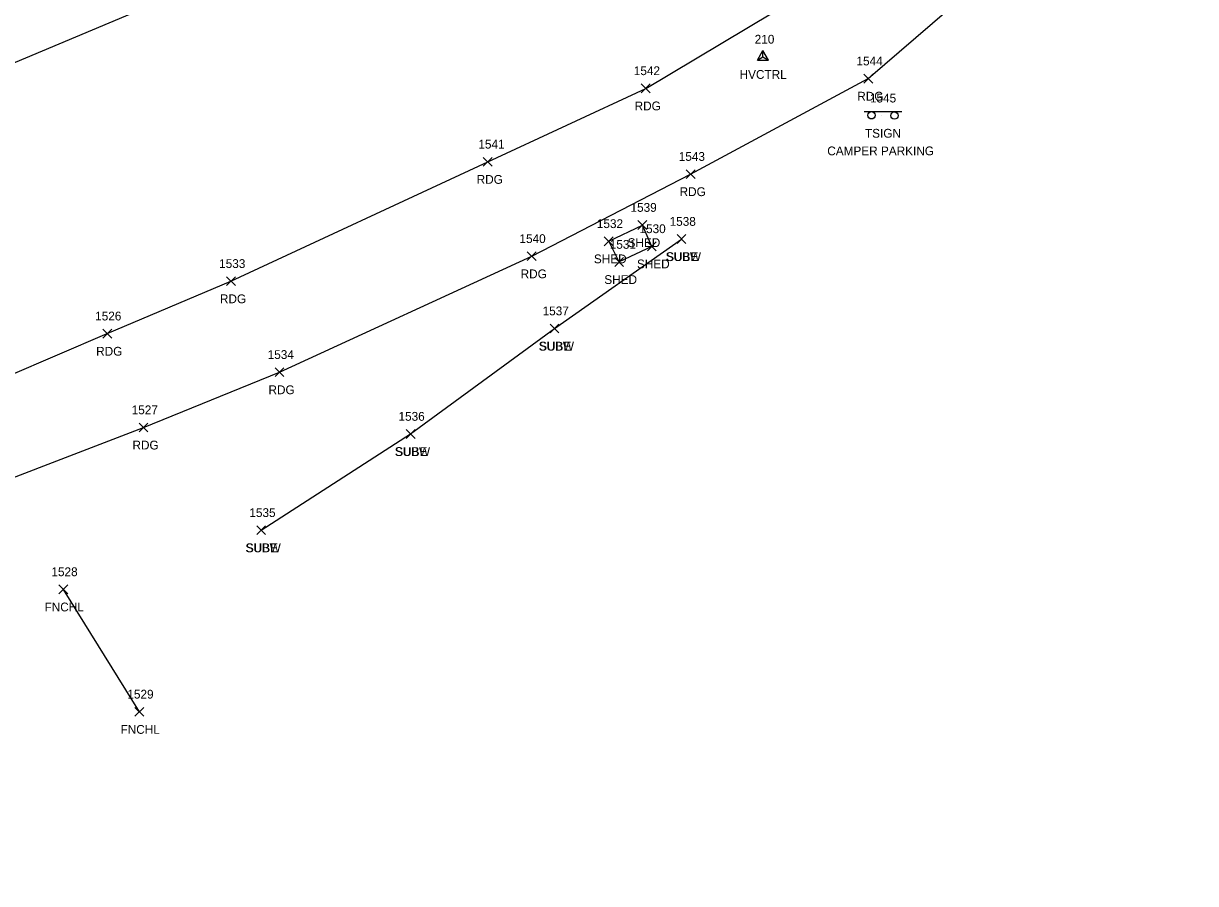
# Model space of a CAD drawing. Extents: x 1481523 to 1489083, y 884156 to 893756.
# Drawn here: x 1486886.1 to 1487152.1, y 887971.3 to 888166.7 of the extents above; entities that cross this region are included whole.
import ezdxf

# ---------------------------------------------------------------- set-up
doc = ezdxf.new("R2010")
doc.units = 0
for name, color, linetype in [('C_A', 7, 'Continuous'), ('C_I', 7, 'Continuous'), ('CPSM', 7, 'Continuous'), ('L_A', 7, 'Continuous'), ('L_I', 7, 'Continuous'), ('L_TIC', 7, 'Continuous'), ('LBC', 7, 'Continuous'), ('LFNC', 7, 'Continuous'), ('P_A', 7, 'Continuous'), ('P_I', 7, 'Continuous'), ('P_TIC', 7, 'Continuous'), ('PEU', 7, 'Continuous'), ('S_A', 7, 'Continuous'), ('S_C', 7, 'Continuous'), ('S_I', 7, 'Continuous'), ('SSGN', 7, 'Continuous'), ('U_A', 7, 'Continuous'), ('U_I', 7, 'Continuous'), ('U_TIC', 7, 'Continuous'), ('UE', 7, 'Continuous'), ('UW', 7, 'Continuous')]:
    doc.layers.add(name, color=color, linetype=linetype)

msp = doc.modelspace()

# ---------------------------------------------------------------- linework, layer by layer
at = {"layer": 'CPSM'}
for p, q in [((1487052.67, 888158.34), (1487053.92, 888160.5)), ((1487052.67, 888158.34), (1487053.92, 888159.06)), ((1487052.67, 888158.34), (1487055.17, 888158.34)), ((1487055.17, 888158.34), (1487053.92, 888160.5)), ((1487053.92, 888159.06), (1487053.92, 888160.5)), ((1487053.92, 888159.06), (1487053.92, 888159.06)), ((1487053.92, 888159.06), (1487055.17, 888158.34))]:
    msp.add_line(p, q, dxfattribs=at)
at = {"layer": 'L_TIC'}
for points in [[(1487025.55, 888119.87), (1487027.55, 888121.87)], [(1487027.55, 888119.87), (1487025.55, 888121.87)], [(1487025.55, 888119.87), (1487027.55, 888121.87)], [(1487027.55, 888119.87), (1487025.55, 888121.87)], [(1487017.9, 888116.18), (1487019.9, 888118.18)], [(1487019.9, 888116.18), (1487017.9, 888118.18)], [(1487027.67, 888115.03), (1487029.67, 888117.03)], [(1487029.67, 888115.03), (1487027.67, 888117.03)], [(1487027.67, 888115.03), (1487029.67, 888117.03)], [(1487029.67, 888115.03), (1487027.67, 888117.03)], [(1487020.27, 888111.48), (1487022.27, 888113.48)], [(1487022.27, 888111.48), (1487020.27, 888113.48)], [(1486894.1, 888037.13), (1486896.1, 888039.13)], [(1486896.1, 888037.13), (1486894.1, 888039.13)], [(1486911.35, 888009.33), (1486913.35, 888011.33)], [(1486913.35, 888009.33), (1486911.35, 888011.33)]]:
    msp.add_lwpolyline(points, dxfattribs=at)
at = {"layer": 'LBC'}
for points in [[(1487028.67, 888116.03), (1487021.27, 888112.48), (1487018.9, 888117.18), (1487026.55, 888120.87)], [(1487028.67, 888116.03), (1487026.55, 888120.87)]]:
    msp.add_lwpolyline(points, dxfattribs=at)
at = {"layer": 'LFNC'}
for points in [[(1487123.63, 888696.4), (1487124.91, 888638.27), (1487126.15, 888568.63), (1487127.36, 888492.8), (1487107.41, 888449.36), (1487090.77, 888413.6), (1487074.34, 888378.07), (1487054.02, 888334.46), (1487033.84, 888290.91), (1487013.45, 888247.02), (1487001.64, 888221.58), (1486993.21, 888204.38), (1486939.48, 888181.13), (1486867.52, 888150.81), (1486821.88, 888131.48), (1486777.19, 888112.51), (1486741.33, 888097.33), (1486705.19, 888082.4), (1486701.15, 888103.56), (1486696.51, 888133.19), (1486722.31, 888152.64)], [(1486895.1, 888038.13), (1486912.35, 888010.33)]]:
    msp.add_lwpolyline(points, dxfattribs=at)
at = {"layer": 'P_TIC'}
for points in [[(1487076.83, 888153.12), (1487078.83, 888155.12)], [(1487078.83, 888153.12), (1487076.83, 888155.12)], [(1487026.3, 888150.91), (1487028.3, 888152.91)], [(1487028.3, 888150.91), (1487026.3, 888152.91)], [(1486990.44, 888134.23), (1486992.44, 888136.23)], [(1486992.44, 888134.23), (1486990.44, 888136.23)], [(1487036.5, 888131.44), (1487038.5, 888133.44)], [(1487038.5, 888131.44), (1487036.5, 888133.44)], [(1487000.42, 888112.78), (1487002.42, 888114.78)], [(1487002.42, 888112.78), (1487000.42, 888114.78)], [(1486932.17, 888107.11), (1486934.17, 888109.11)], [(1486934.17, 888107.11), (1486932.17, 888109.11)], [(1486904.09, 888095.2), (1486906.09, 888097.2)], [(1486906.09, 888095.2), (1486904.09, 888097.2)], [(1486943.19, 888086.45), (1486945.19, 888088.45)], [(1486945.19, 888086.45), (1486943.19, 888088.45)], [(1486912.32, 888073.9), (1486914.32, 888075.9)], [(1486914.32, 888073.9), (1486912.32, 888075.9)]]:
    msp.add_lwpolyline(points, dxfattribs=at)
at = {"layer": 'PEU'}
for points in [[(1486693.43, 888030.65), (1486711.45, 888026.25), (1486729.25, 888026.61), (1486741.64, 888030.11), (1486776.57, 888043.35), (1486813.61, 888057.74), (1486859.9, 888076.88), (1486905.09, 888096.2), (1486933.17, 888108.11), (1486991.44, 888135.23), (1487027.3, 888151.91), (1487061.93, 888172.65), (1487100.02, 888202.76), (1487134.5, 888235.55), (1487174.13, 888267.94)], [(1486703.84, 887971.32), (1486720.57, 887989.63), (1486732.92, 887997.98), (1486752, 888006.2), (1486785.58, 888023.44), (1486824.24, 888039.92), (1486864.7, 888056.22), (1486913.32, 888074.9), (1486944.19, 888087.45), (1487001.42, 888113.78), (1487037.5, 888132.44), (1487077.83, 888154.12), (1487114.03, 888185.38), (1487147.32, 888221.55), (1487184.59, 888252.66)]]:
    msp.add_lwpolyline(points, dxfattribs=at)
at = {"layer": 'SSGN'}
for p, q in [((1487076.88, 888146.62), (1487085.47, 888146.62)), ((1487080.9, 888145.72), (1487080.9, 888145.72))]:
    msp.add_line(p, q, dxfattribs=at)
for centre in [(1487078.54, 888145.79), (1487083.75, 888145.72)]:
    msp.add_circle(centre, 0.833, dxfattribs=at)
at = {"layer": 'U_TIC'}
for points in [[(1487034.42, 888116.69), (1487036.42, 888118.69)], [(1487036.42, 888116.69), (1487034.42, 888118.69)], [(1487034.42, 888116.69), (1487036.42, 888118.69)], [(1487036.42, 888116.69), (1487034.42, 888118.69)], [(1487005.59, 888096.36), (1487007.59, 888098.36)], [(1487007.59, 888096.36), (1487005.59, 888098.36)], [(1487005.59, 888096.36), (1487007.59, 888098.36)], [(1487007.59, 888096.36), (1487005.59, 888098.36)], [(1486972.94, 888072.42), (1486974.94, 888074.42)], [(1486974.94, 888072.42), (1486972.94, 888074.42)], [(1486972.94, 888072.42), (1486974.94, 888074.42)], [(1486974.94, 888072.42), (1486972.94, 888074.42)], [(1486939.04, 888050.56), (1486941.04, 888052.56)], [(1486941.04, 888050.56), (1486939.04, 888052.56)], [(1486939.04, 888050.56), (1486941.04, 888052.56)], [(1486941.04, 888050.56), (1486939.04, 888052.56)]]:
    msp.add_lwpolyline(points, dxfattribs=at)
at = {"layer": 'UE'}
msp.add_lwpolyline([(1486940.04, 888051.56), (1486973.94, 888073.42), (1487006.59, 888097.36), (1487035.42, 888117.69)], dxfattribs=at)
at = {"layer": 'UW'}
msp.add_lwpolyline([(1486940.04, 888051.56), (1486973.94, 888073.42), (1487006.59, 888097.36), (1487035.42, 888117.69)], dxfattribs=at)

# ---------------------------------------------------------------- texts
at = {"layer": 'C_A'}
msp.add_text('HVCTRL', height=2, dxfattribs=at).set_placement((1487048.61, 888154.06))
at = {"layer": 'C_I'}
msp.add_text('210', height=2, dxfattribs=at).set_placement((1487052.04, 888162.06))
at = {"layer": 'L_A'}
for s, p in [('SHED', (1487023.18, 888115.87)), ('SHED', (1487023.18, 888115.87)), ('SHED', (1487015.54, 888112.18)), ('SHED', (1487025.31, 888111.03)), ('SHED', (1487025.31, 888111.03)), ('SHED', (1487017.9, 888107.48)), ('FNCHL', (1486890.85, 888033.13)), ('FNCHL', (1486908.1, 888005.33))]:
    msp.add_text(s, height=2, dxfattribs=at).set_placement(p)
at = {"layer": 'L_I'}
for s, p in [('1539', (1487023.85, 888123.87)), ('1539', (1487023.85, 888123.87)), ('1532', (1487016.21, 888120.18)), ('1530', (1487025.89, 888119.03)), ('1530', (1487025.89, 888119.03)), ('1531', (1487019.14, 888115.48)), ('1528', (1486892.41, 888041.13)), ('1529', (1486909.65, 888013.33))]:
    msp.add_text(s, height=2, dxfattribs=at).set_placement(p)
at = {"layer": 'P_A'}
for p in [(1487075.32, 888149.12), (1487024.78, 888146.91), (1486988.93, 888130.23), (1487034.99, 888127.44), (1486998.91, 888108.78), (1486930.66, 888103.11), (1486902.57, 888091.2), (1486941.68, 888082.45), (1486910.81, 888069.9)]:
    msp.add_text('RDG', height=2, dxfattribs=at).set_placement(p)
at = {"layer": 'P_I'}
for s, p in [('1544', (1487075.14, 888157.12)), ('1542', (1487024.6, 888154.91)), ('1541', (1486989.32, 888138.23)), ('1543', (1487034.8, 888135.44)), ('1540', (1486998.65, 888116.78)), ('1533', (1486930.48, 888111.11)), ('1526', (1486902.34, 888099.2)), ('1534', (1486941.5, 888090.45)), ('1527', (1486910.63, 888077.9))]:
    msp.add_text(s, height=2, dxfattribs=at).set_placement(p)
at = {"layer": 'S_A'}
msp.add_text('TSIGN', height=2, dxfattribs=at).set_placement((1487077.07, 888140.7))
at = {"layer": 'S_C'}
msp.add_text('CAMPER PARKING', height=2, dxfattribs=at).set_placement((1487068.51, 888136.7))
at = {"layer": 'S_I'}
msp.add_text('1545', height=2, dxfattribs=at).set_placement((1487078.2, 888148.7))
at = {"layer": 'U_A'}
for s, p in [('SUBW', (1487031.83, 888112.69)), ('SUBE', (1487031.96, 888112.69)), ('SUBW', (1487003, 888092.36)), ('SUBE', (1487003.13, 888092.36)), ('SUBW', (1486970.34, 888068.42)), ('SUBE', (1486970.47, 888068.42)), ('SUBW', (1486936.45, 888046.56)), ('SUBE', (1486936.57, 888046.56))]:
    msp.add_text(s, height=2, dxfattribs=at).set_placement(p)
at = {"layer": 'U_I'}
for s, p in [('1538', (1487032.73, 888120.69)), ('1538', (1487032.73, 888120.69)), ('1537', (1487003.9, 888100.36)), ('1537', (1487003.9, 888100.36)), ('1536', (1486971.19, 888076.42)), ('1536', (1486971.19, 888076.42)), ('1535', (1486937.34, 888054.56)), ('1535', (1486937.34, 888054.56))]:
    msp.add_text(s, height=2, dxfattribs=at).set_placement(p)

doc.saveas('drawing.dxf')
